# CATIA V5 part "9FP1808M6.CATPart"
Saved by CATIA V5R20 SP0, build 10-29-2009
Part number: 9FP1808M6
Revision: ANY
Definition: UNKNOWN
Nomenclature: 9FP1808M6
Source: Unknown
Bounding box of the stored display mesh (mm): x -8.9 to 8.9, y 0 to 8, z -8.9 to 8.9
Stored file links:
  C:\Users\Utente\Desktop\IO LAVORO\3D X SITO CF\CUMSA\3D files PW\pw101630\pw101630_ejection\9FP1808M6.CATPart
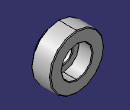
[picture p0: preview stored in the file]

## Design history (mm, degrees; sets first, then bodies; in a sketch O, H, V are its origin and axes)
Body1 "Chaflán1" (main body)
  Solid1: solid without history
